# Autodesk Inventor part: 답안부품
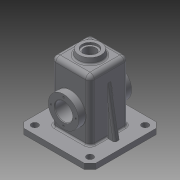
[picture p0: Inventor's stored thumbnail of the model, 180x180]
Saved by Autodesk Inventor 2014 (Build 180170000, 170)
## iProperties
Created: 2016-02
Part Number: 답안부품
Material: 일반
Document SubType Name: Modeling
Designer: 703-6
Density: 1 g/cm^3
Appearance: 기본값
Author: 703-6
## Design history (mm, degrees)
sketch "스케치1"
  geometry: L1 (-65, 65)-(65, 65); L2 (65, 65)-(65, -65); L3 (65, -65)-(-65, -65); L4 (-65, -65)-(-65, 65); 1 further point
  constraints: 8 end point, 2 parallel, 1 horizontal, 1 perpendicular
  dimensions: "d0" = 130 distance of L1.start L1.end; "d1" = 130 distance of L1.end L2.end; "d2" = 65 distance from line of point (0, 0) L1; "d3" = 65 distance from line of point (0, 0) L2
extrude "돌출1" new body sketch "스케치1" distance "d4" = 10; taper "d5" = 0 deg
sketch "스케치2"
  geometry: L1 (-35, 35)-(35, 35); L2 (35, 35)-(35, -35); L3 (35, -35)-(-35, -35); L4 (-35, -35)-(-35, 35); 1 further point
  constraints: 8 end point, 2 parallel, 1 horizontal, 1 perpendicular
  dimensions: "d6" = 70 distance of L1.start L1.end; "d7" = 70 distance of L3.end L1.start; "d8" = 35 distance from line of point (0, 0) L1; "d9" = 35 distance from line of point (0, 0) L4
extrude "돌출2" join sketch "스케치2" distance "d10" = 110; taper "d11" = 0 deg
sketch "스케치3"
  geometry: L1 (65, 10)-(65, 0) reference; L2 (65, 0)-(-65, 0) reference; L3 (-65, 0)-(-65, 10) reference; L4 (-65, 10)-(-35, 10) reference; L5 (-35, 10)-(-35, 120) reference; L6 (-35, 120)-(35, 120) reference; L7 (35, 120)-(35, 10) reference; L8 (35, 10)-(65, 10) reference; L9 (-50, 10)-(-35, 95.069); L10 (-50, 10)-(-35, 10); L11 (-35.07, 94.672)-(-35.07, 10); 1 further point
  constraints: 6 end point, 4 point on line, 2 perpendicular
  dimensions: "d12" = 15 distance from line of L9.start L3; "d13" = 10 distance from line of L9.start L2; "d14" = 10 deg angle of L9 L3; "d15" = 35 distance from line of point (0, 0) L5 (derived); "d16" = 94.67177 distance from line of L2 L11.start
extrude "돌출3" join sketch "스케치3" stored distance "d17" = 10; taper "d18" = 0 deg
sketch "스케치4"
  geometry: L1 (65, 10)-(65, 0) reference; L2 (65, 0)-(-65, 0) reference; L3 (-65, 0)-(-65, 10) reference; L4 (-65, 10)-(-50, 10) reference; L5 (-50, 10)-(-35.07, 94.672) reference; L6 (-35.07, 94.672)-(-35.07, 10) reference; L7 (-35.07, 10)-(-35, 10) reference; L8 (-35, 10)-(-35, 120) reference; L9 (-35, 120)-(35, 120) reference; L10 (35, 120)-(35, 10) reference; L11 (35, 10)-(35.07, 10) reference; L12 (35.07, 10)-(35.07, 94.672) reference; L13 (35.07, 94.672)-(50, 10) reference; L14 (50, 10)-(65, 10) reference; L15 (-30, 115)-(30.07, 115); L16 (30.07, 115)-(30.07, 0); L17 (30.07, 0)-(-30, 0); L18 (-30, 0)-(-30, 115); 1 further point
  constraints: 8 end point, 2 parallel, 1 horizontal, 1 perpendicular
  dimensions: "d19" = 5 distance between parallel lines of L9 L15; "d20" = 5 distance from line of L12.end L16; "d21" = 5 distance between parallel lines of L8 L18; "d22" = 0 distance between parallel lines of L17 L2
extrude "돌출4" cut sketch "스케치4" stored distance "d23" = 60; taper "d24" = 0 deg
sketch "스케치5"
  geometry: L1 (65, 10)-(65, 0) reference; L2 (65, 0)-(30, 0) reference; L3 (30, 0)-(30, 115) reference; L4 (30, 115)-(-30, 115) reference; L5 (-30, 115)-(-30, 0) reference; L6 (-30, 0)-(-65, 0) reference; L7 (-65, 0)-(-65, 10) reference; L8 (-65, 10)-(-35, 10) reference; L9 (-35, 10)-(-35, 120) reference; L10 (-35, 120)-(35, 120) reference; L11 (35, 120)-(35, 10) reference; L12 (35, 10)-(65, 10) reference; L13 (30, 82.5)-(23, 75.5); L14 (30, 82.5)-(30, 55); L15 (30, 55)-(23, 55); L16 (23, 75.5)-(23, 55); 1 further point
  constraints: 8 end point, 1 parallel, 1 perpendicular, 1 point on line
  dimensions: "d26" = 135 deg angle of L13 L3; "d28" = 7 horizontal distance of L13.start L13.end; "d29" = 55 distance from line of point (0, 0) L15; "d30" = 27.5 vertical distance of L15.end L13.start; "d31" = 30 distance from line of point (0, 0) L14
revolve "회전1" sketch "스케치5" stored, may be unused: angle "d32" = 90 deg
sketch "스케치6"
  geometry: L1 (-30, 10)-(100, 10) reference; C1 r 27.5 at (35, -45); 2 further points
  constraints: 1 centre point, 1 midpoint, 1 vertical alignment
  dimensions: "d33" = 55 diameter of C1; "d34" = 55 distance from line of C1.centre L1
extrude "돌출5" join sketch "스케치6" distance "d35" = 13; taper "d36" = 0 deg
sketch "스케치7"
  geometry: C1 r 27.5 at (0, 0) reference; 1 further point
hole "구멍1" sketch "스케치7" at (0, 0) diameter "d37" = 32; stored, may be unused: countersink angle "d41" = 90 deg, drill point angle "d43" = 118 deg; dims "d38" = 6, "d39" = 4, "d40" = 2, "d42" = 8
sketch "스케치8"
  geometry: C1 r 16 at (0, 0) reference; 2 further points
  dimensions: "d44" = 22.5 distance of point (0, -22.5) C1.centre; "d45" = 0 horizontal distance of C1.centre point (0, -22.5)
hole "구멍2" sketch "스케치8" at (0, -22.5) diameter "d46" = 3.242; stored, may be unused: countersink angle "d50" = 82 deg, drill point angle "d52" = 118 deg; dims "d47" = 8, "d48" = 3.023, "d49" = 2, "d51" = 10
sketch "스케치9"
  geometry: L1 (21.763, 120)-(20, 130); L2 (-35, 120)-(35, 120) reference; L3 (35, 10)-(35, 120) reference; L4 (20, 130)-(0, 130); L5 (21.763, 120)-(0, 120); L6 (0, 120)-(0, 130); 1 further point
  constraints: 8 end point, 2 perpendicular, 1 midpoint
  dimensions: "d56" = 10 vertical distance of L1.start L1.end; "d57" = 0 distance from line of L1.start L2; "d61" = 10 deg angle of L1 L3; "d62" = 20 horizontal distance of point (0, 0) L1.end; "d63" = 20 distance from line of L1.end L6
revolve "회전2" sketch "스케치9" stored, may be unused: angle "d64" = 90 deg
sketch "스케치10"
  geometry: C1 r 20 at (0, 0) reference
hole "구멍3" sketch "스케치10" at (0, 0) diameter "d65" = 21; stored, may be unused: countersink angle "d69" = 82 deg, drill point angle "d71" = 118 deg; dims "d66" = 6, "d67" = 28, "d68" = 4, "d70" = 8
fillet "모깎기1" dims "d72" = 3
sketch "스케치11"
  geometry: L1 (65, 65)-(-65, 65) reference; L2 (-65, 65)-(-65, -65) reference; C1 r 6 at (-50, 50); 1 further point
  constraints: 1 centre point
  dimensions: "d73" = 12 diameter of C1; "d74" = 15 distance from line of C1.centre L1; "d75" = 15 distance from line of C1.centre L2
extrude "돌출6" cut sketch "스케치11" distance "d76" = 10; taper "d77" = 0 deg
fillet "모깎기2" dims "d84" = 3
fillet "모깎기3" dims "d85" = 8
fillet "모깎기4" dims "d86" = 3
fillet "모깎기5" dims "d87" = 3
chamfer "모따기1" distance "d88" = 10; stored, may be unused: second distance "d89" = 2, angle "d90" = 45 deg
chamfer "모따기2" distance "d91" = 10; stored, may be unused: second distance "d92" = 2, angle "d93" = 45 deg
chamfer "모따기3" distance "d94" = 10; stored, may be unused: second distance "d95" = 2, angle "d96" = 45 deg
fillet "모깎기6" dims "d97" = 0.5
fillet "모깎기7" dims "d98" = 0.5
fillet "모깎기8" dims "d99" = 0.5
sketch "스케치12"
  geometry: L1 (44.216, 6.998)-(9.784, 6.998); L2 (9.784, 6.998)-(9.784, 17.002); L3 (9.784, 17.002)-(44.216, 17.002); L4 (44.216, 17.002)-(44.216, 6.998); L5 (-8, 99)-(-8, 0) reference; L6 (47, -18)-(7, -18) reference; 3 further points
  constraints: 2 midpoint, 2 other
  dimensions: "d100" = 35 distance from line of point (27, 6.998) L5; "d101" = 30 distance from line of point (9.784, 12) L6; "d102" = 24.99814 distance from line of point (27, 6.998) L6; "d103" = 17.78431 distance from line of L5 point (9.784, 12)
feature "엠보싱1" sketch "스케치12" dims "d12" = 15, "d13" = 10, "d14" = 10 deg, "d16" = 94.67177, "d104" = 0.5, "d105" = 0
chamfer "모따기4" distance "d106" = 1; stored, may be unused: second distance "d107" = 2, angle "d108" = 45 deg
chamfer "모따기5" distance "d109" = 1; stored, may be unused: second distance "d110" = 2, angle "d111" = 45 deg
node "솔리드1"
mirror "대칭1"
mirror "대칭2"
pattern_circular "원형 패턴1" dims angle "d54" = 360 deg
mirror "대칭3"
pattern_linear "직사각형 패턴1" dims "d80" = 100
node "절단 모서리 투영1"
node "절단 모서리 투영2"
node "절단 모서리 투영3"
other parameters: "d25" = 55, "d27" = 27.5
